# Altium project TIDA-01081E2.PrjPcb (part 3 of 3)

## Sheet TIDA-01081E2_Pre-Boost.SchDoc: Pre-Boost
size 431 x 279 mm; Date: Not shown in title block; ApprovedBy: Not shown in title block; CheckedBy: Not shown in title block; Author: Not shown in title block; CompanyName: Not shown in title block; DrawnBy: SG; Engineer: Not shown in title block; Organization: Not shown in title block; Address1: Not shown in title block; Address2: Not shown in title block; Address3: Not shown in title block; Address4: Not shown in title block; DocumentNumber: 3; Revision: Use project parameter SCH_Rev; SheetNumber: 3; SheetTotal: 8; PageSetup: Record=PageOptions¦CenterHorizontal=True¦CenterVertical=True¦PrintScale=0.94¦XCorrection=1.00¦YCorrection=1.00¦PrintKind=0¦BorderSize=5000000¦LeftOffset=0¦BottomOffset=0¦Orientation=2¦PaperLength=4200¦PaperWidth=2970¦Scale=100¦PaperSource=7¦PrintQuality=600¦MediaType=1¦DitherType=10¦PrintScaleMode=1¦PaperKind=A3¦PaperIndex=8
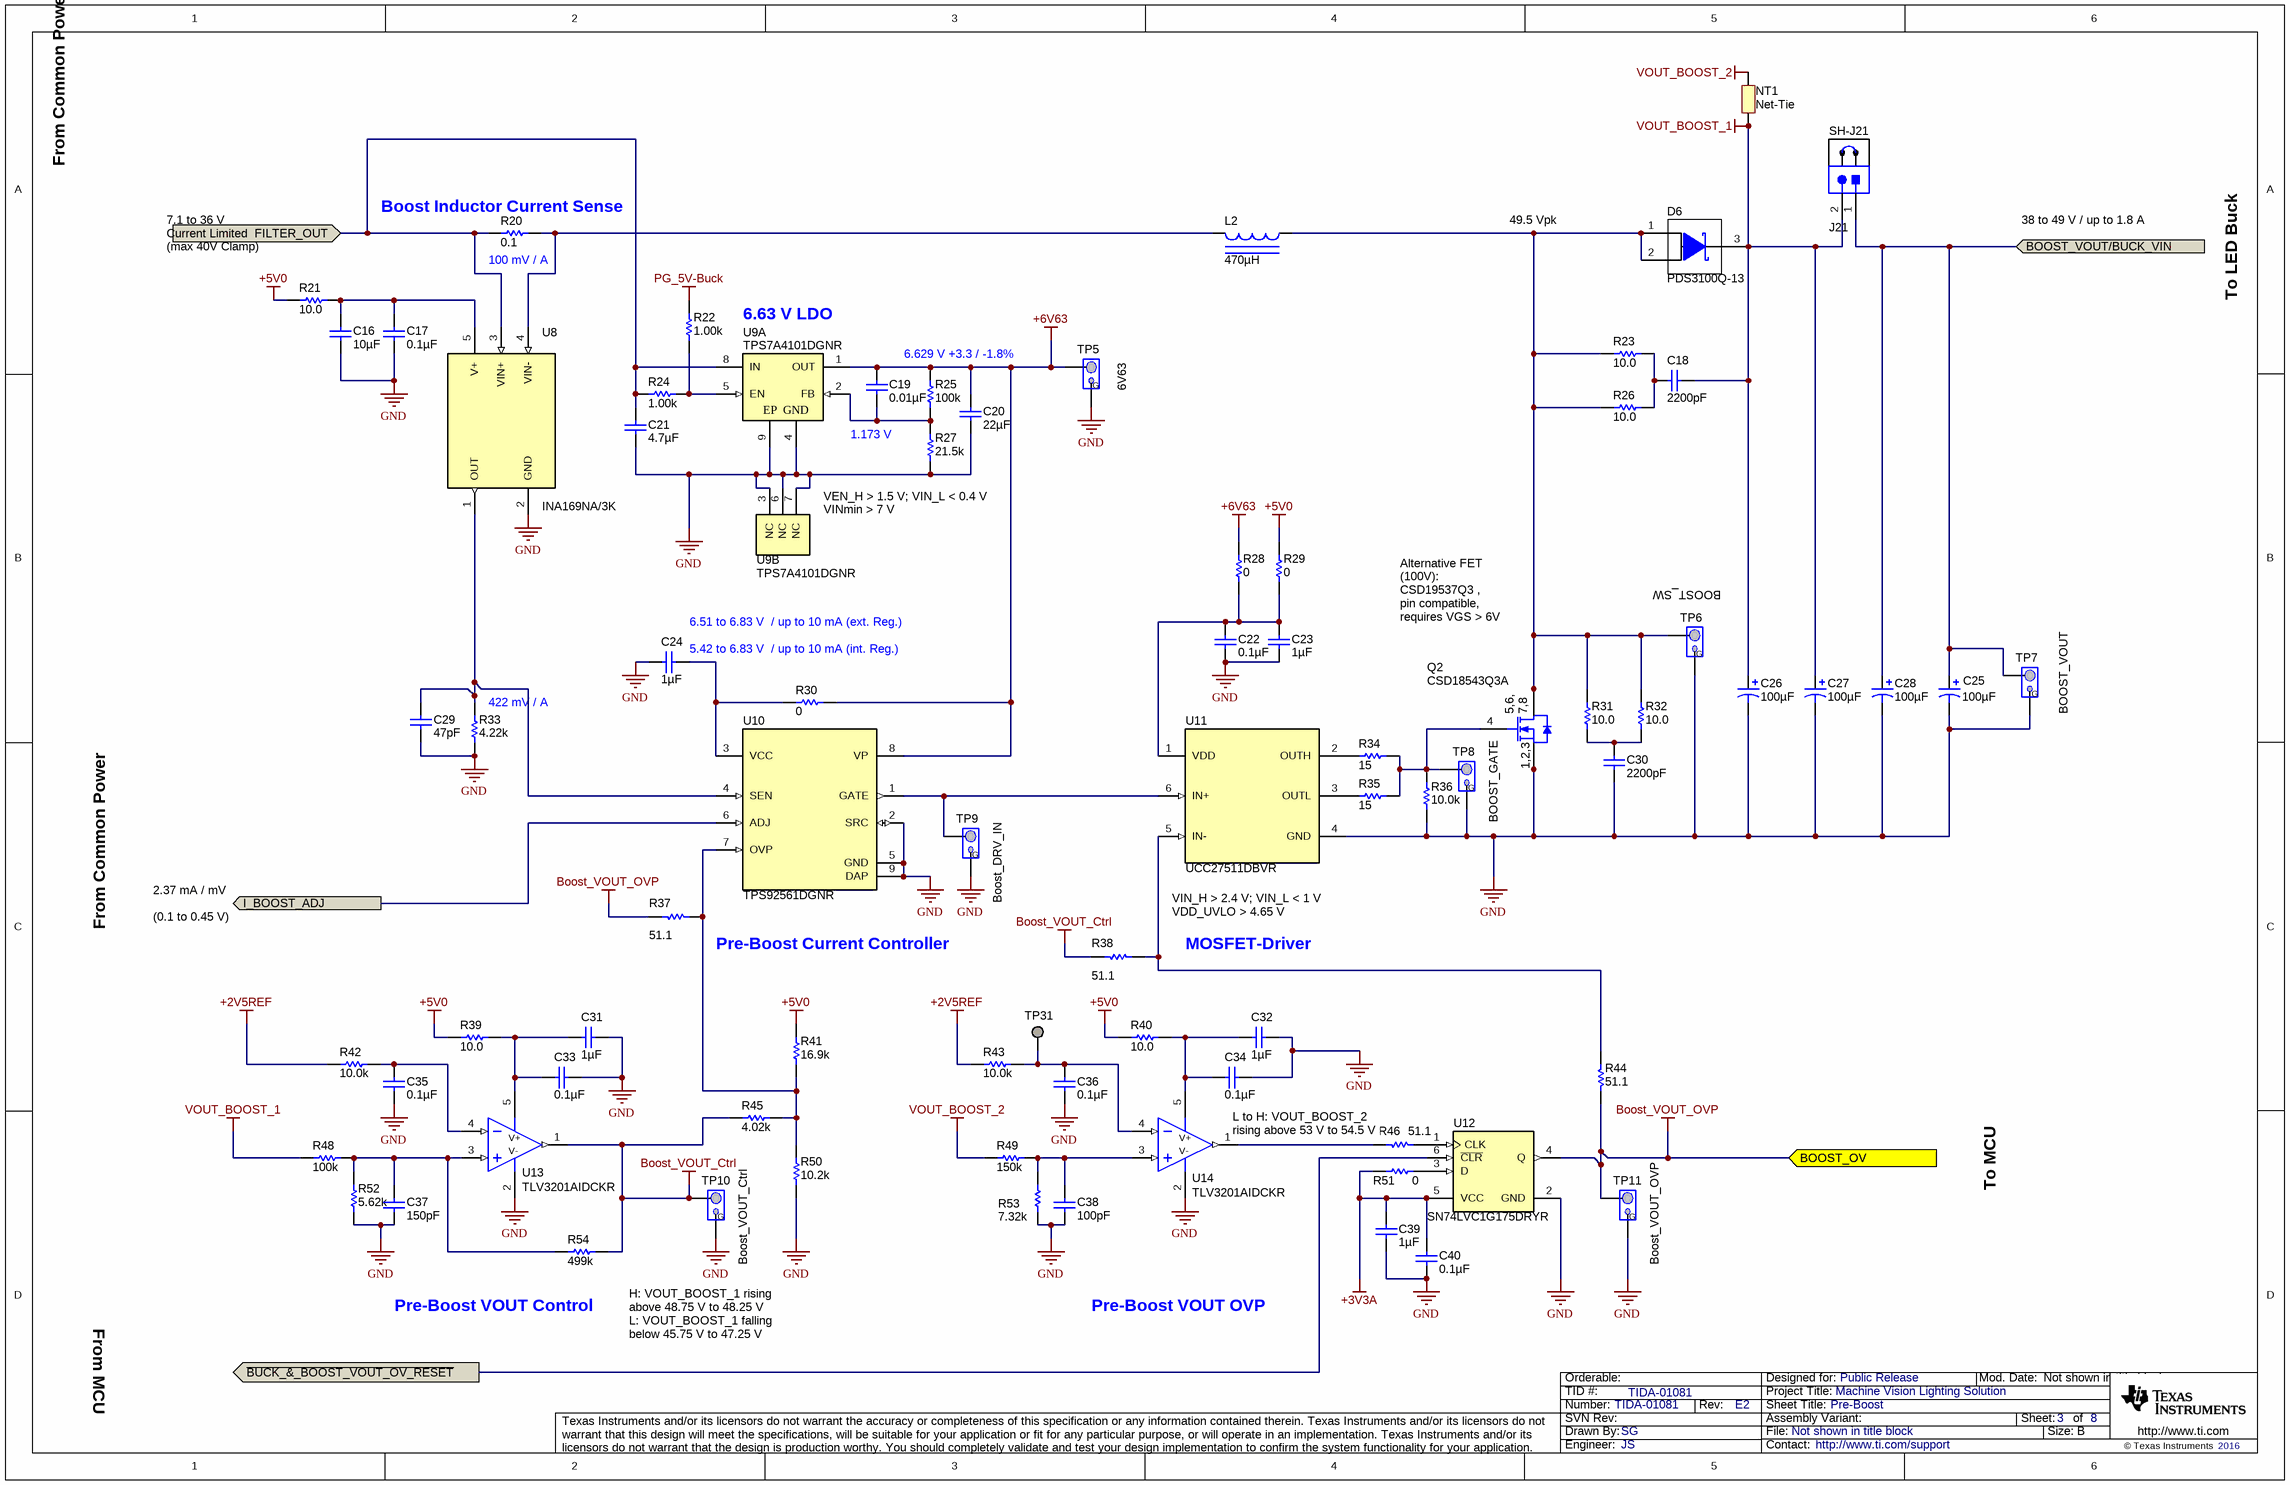
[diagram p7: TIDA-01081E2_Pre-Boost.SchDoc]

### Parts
C16  ValueDisplayed: 10µF  [0603_120]  (hidden comment: ZRB18AD71A106KE01L)
C17  ValueDisplayed: 0.1µF  [0603_HV]  (hidden comment: GCM188R71C104KA37J)
C18  ValueDisplayed: 2200pF  [0603]  (hidden comment: CGA3E2X7R2A222K080AA)
C19  ValueDisplayed: 0.01µF  [0603]  (hidden comment: CL10B103KB8NCNC)
C20  ValueDisplayed: 22µF  [1206_180]  (hidden comment: GRM31CR61E226KE15L)
C21  ValueDisplayed: 4.7µF  [1210_270]  (hidden comment: GRM32ER71K475KE14L)
C22  ValueDisplayed: 0.1µF  [0603_HV]  (hidden comment: GCM188R71C104KA37J)
C23  ValueDisplayed: 1µF  [0603]  (hidden comment: GRM188R71C105KE15D)
C24  ValueDisplayed: 1µF  [0603]  (hidden comment: GRM188R71C105KE15D)
C25  ValueDisplayed: 100µF  [SM_RADIAL_G]  (hidden comment: EEE-FK1J101P)
C26  ValueDisplayed: 100µF  [SM_RADIAL_G]  (hidden comment: EEE-FK1J101P)
C27  ValueDisplayed: 100µF  [SM_RADIAL_G]  (hidden comment: EEE-FK1J101P)
C28  ValueDisplayed: 100µF  [SM_RADIAL_G]  (hidden comment: EEE-FK1J101P)
C29  ValueDisplayed: 47pF  [0603]  (hidden comment: CGA3E2C0G1H470J080AA)
C30  ValueDisplayed: 2200pF  [0603]  (hidden comment: CGA3E2X7R2A222K080AA)
C31  ValueDisplayed: 1µF  [0603S]  (hidden comment: GRM188R71C105KE15D)
C32  ValueDisplayed: 1µF  [0603]  (hidden comment: GRM188R71C105KE15D)
C33  ValueDisplayed: 0.1µF  [0603_HV]  (hidden comment: GCM188R71C104KA37J)
C34  ValueDisplayed: 0.1µF  [0603_HV]  (hidden comment: GCM188R71C104KA37J)
C35  ValueDisplayed: 0.1µF  [0603_HV]  (hidden comment: GCM188R71C104KA37J)
C36  ValueDisplayed: 0.1µF  [0603_HV]  (hidden comment: GCM188R71C104KA37J)
C37  ValueDisplayed: 150pF  [0603]  (hidden comment: C0603C151J5GACTU)
C38  ValueDisplayed: 100pF  [0603]  (hidden comment: 06035A101JAT2A)
C39  ValueDisplayed: 1µF  [0603]  (hidden comment: GRM188R71C105KE15D)
C40  ValueDisplayed: 0.1µF  [0603_HV]  (hidden comment: GCM188R71C104KA37J)
D6  PDS3100Q-13  [PowerDI5]
J21  61300211121  [WURTH_61300211121]  (value not drawn)
L2  ValueDisplayed: 470µH  [WE-PD_1210]  (hidden comment: 7447709471)
NT1  Net-Tie  [Net-Tie_10mil]  (net tie, no BOM)
Q2  CSD18543Q3A  [DNH0008A]
R20  ValueDisplayed: 0.1  [KRL1220]  (hidden comment: KRL1220E-M-R100-F-T5)
R21  ValueDisplayed: 10.0  [0603]  (hidden comment: RC0603FR-0710RL)
R22  ValueDisplayed: 1.00k  [0603]  (hidden comment: RC0603FR-071KL)
R23  ValueDisplayed: 10.0  [0805_HV]  (hidden comment: ERJ-P06F10R0V)
R24  ValueDisplayed: 1.00k  [0603]  (hidden comment: RC0603FR-071KL)
R25  ValueDisplayed: 100k  [0603_HR]  (hidden comment: RR0816P-104-D)
R26  ValueDisplayed: 10.0  [0805_HV]  (hidden comment: ERJ-P06F10R0V)
R27  ValueDisplayed: 21.5k  [0603_HR]  (hidden comment: RR0816P-2152-D-33C)
R28  ValueDisplayed: 0  [0603]  (hidden comment: RC0603JR-070RL)
R29  ValueDisplayed: 0  [0603]  (hidden comment: RC0603JR-070RL)
R30  ValueDisplayed: 0  [0603]  (hidden comment: RC0603JR-070RL)
R31  ValueDisplayed: 10.0  [0805_HV]  (hidden comment: ERJ-P06F10R0V)
R32  ValueDisplayed: 10.0  [0805_HV]  (hidden comment: ERJ-P06F10R0V)
R33  ValueDisplayed: 4.22k  [0603]  (hidden comment: CRCW06034K22FKEA)
R34  ValueDisplayed: 15  [0603]  (hidden comment: CRCW060315R0JNEA)
R35  ValueDisplayed: 15  [0603]  (hidden comment: CRCW060315R0JNEA)
R36  ValueDisplayed: 10.0k  [0603]  (hidden comment: RC0603FR-0710KL)
R37  ValueDisplayed: 51.1  [0603]  (hidden comment: RC0603FR-0751R1L)
R38  ValueDisplayed: 51.1  [0603]  (hidden comment: RC0603FR-0751R1L)
R39  ValueDisplayed: 10.0  [0603]  (hidden comment: RC0603FR-0710RL)
R40  ValueDisplayed: 10.0  [0603]  (hidden comment: RC0603FR-0710RL)
R41  ValueDisplayed: 16.9k  [0603]  (hidden comment: CRCW060316K9FKEA)
R42  ValueDisplayed: 10.0k  [0603]  (hidden comment: RC0603FR-0710KL)
R43  ValueDisplayed: 10.0k  [0603]  (hidden comment: RC0603FR-0710KL)
R44  ValueDisplayed: 51.1  [0603]  (hidden comment: RC0603FR-0751R1L)
R45  ValueDisplayed: 4.02k  [0603]  (hidden comment: CRCW06034K02FKEA)
R46  ValueDisplayed: 51.1  [0603]  (hidden comment: RC0603FR-0751R1L)
R48  ValueDisplayed: 100k  [0603]  (hidden comment: RT0603BRD07100KL)
R49  ValueDisplayed: 150k  [0603]  (hidden comment: RG1608P-154-B-T5)
R50  ValueDisplayed: 10.2k  [0603]  (hidden comment: CRCW060310K2FKEA)
R51  ValueDisplayed: 0  [0603]  (hidden comment: RC0603JR-070RL)
R52  ValueDisplayed: 5.62k  [0603]  (hidden comment: RG1608P-5621-B-T5)
R53  ValueDisplayed: 7.32k  [0603]  (hidden comment: RT0603BRD077K32L)
R54  ValueDisplayed: 499k  [0603]  (hidden comment: RT0603DRE07499KL)
SH-J21  969102-0000-DA  [SNT-100-BK-G]  (value not drawn)
TP5  TESTPOINT_PIGTAIL  [TESTPOINT_PIGTAIL]  (value not drawn)  (no BOM)
TP6  TESTPOINT_PIGTAIL  [TESTPOINT_PIGTAIL]  (value not drawn)  (no BOM)
TP7  TESTPOINT_PIGTAIL  [TESTPOINT_PIGTAIL]  (value not drawn)  (no BOM)
TP8  TESTPOINT_PIGTAIL  [TESTPOINT_PIGTAIL]  (value not drawn)  (no BOM)
TP9  TESTPOINT_PIGTAIL  [TESTPOINT_PIGTAIL]  (value not drawn)  (no BOM)
TP10  TESTPOINT_PIGTAIL  [TESTPOINT_PIGTAIL]  (value not drawn)  (no BOM)
TP11  TESTPOINT_PIGTAIL  [TESTPOINT_PIGTAIL]  (value not drawn)  (no BOM)
TP31  TESTPOINT  [TP_SM_1MM]  (value not drawn)  (no BOM)
U8  INA169NA/3K  [DBV0005A_N]
U9  TPS7A4101DGNR  [DGN0008B_N]  (parts A,B of 2)
U10  TPS92561DGNR  [DGN0008D_N]
U11  UCC27511DBVR  [DBV0006A_N]
U12  SN74LVC1G175DRYR  [DRY0006A]
U13  TLV3201AIDCKR  [DCK0005A_N]
U14  TLV3201AIDCKR  [DCK0005A_N]

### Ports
BOOST_OV, BOOST_VOUT/BUCK_VIN, FILTER_OUT, I_BOOST_ADJ, ~{BUCK_&_BOOST_VOUT_OV_RESET}

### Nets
+2V5REF: R42.2 R43.2
+3V3A: C39.2 C40.1 R51.1 U12.5(VCC)
+5V0: R21.1 R29.2 R39.2 R40.2 R41.2
+6V63: C19.1 C20.1 R25.2 R28.2 R30.2 TP5.1 U9.1(OUT) U10.8(VP)
Boost_VOUT_Ctrl: R38.2 R45.1 R54.2 TP10.1 U13.1(OUT)
Boost_VOUT_OVP: R37.2 R44.2 TP11.1 U12.4(Q) ; port BOOST_OV
FILTER_OUT: C21.1 R20.1 R24.1 U8.3(VIN+) U9.8(IN) ; port FILTER_OUT
GND: C16.2 C17.1 C20.2 C21.2 C22.1 C23.1 C24.2 C25.2(-) C26.2(-) C27.2(-) C28.2(-) C29.2 C30.2 C31.1 C32.1 C33.1 C34.1 C35.2 C36.2 C37.1 C38.1 C39.1 C40.2 Q2.1(S) Q2.2(S) Q2.3(S) R27.1 R33.1 R36.1 R50.1 R52.1 R53.1 TP5.2 TP6.2 TP7.2 TP8.2 TP9.2 TP10.2 TP11.2 U8.2(GND) U9.3(NC) U9.4(GND) U9.6(NC) U9.7(NC) U9.9(EP) U10.2(SRC) U10.5(GND) U10.9(DAP) U11.4(GND) U12.2(GND) U13.2(V-) U14.2(V-)
PG_5V-Buck: R22.1
VOUT_BOOST_1: C18.2 C26.1(+) C27.1(+) D6.3(K) J21.2 NT1.1 R48.1
VOUT_BOOST_2: NT1.2 R49.1
~{BUCK_&_BOOST_VOUT_OV_RESET}: U12.6(~{CLR}) ; port ~{BUCK_&_BOOST_VOUT_OV_RESET}
BOOST_VOUT/BUCK_VIN: C25.1(+) C28.1(+) J21.1 TP7.1 ; port BOOST_VOUT/BUCK_VIN
I_BOOST_ADJ: U10.6(ADJ) ; port I_BOOST_ADJ
NetC16_1: C16.1 C17.2 R21.2 U8.5(V+)
NetC18_1: C18.1 R23.1 R26.1
NetC19_2: C19.2 R25.1 R27.2 U9.2(FB)
NetC22_2: C22.2 C23.2 R28.1 R29.1 U11.1(VDD)
NetC24_1: C24.1 R30.1 U10.3(VCC)
NetC29_1: C29.1 R33.2 U8.1(OUT) U10.4(SEN)
NetC30_1: C30.1 R31.1 R32.1
NetC31_2: C31.2 C33.2 R39.1 U13.5(V+)
NetC32_2: C32.2 C34.2 R40.1 U14.5(V+)
NetC35_1: C35.1 R42.1 U13.4(IN-)
NetC36_1: C36.1 R43.1 TP31.1 U14.4(IN-)
NetC37_2: C37.2 R48.2 R52.2 R54.1 U13.3(IN+)
NetC38_2: C38.2 R49.2 R53.2 U14.3(IN+)
NetD6_1: D6.1(A) D6.2(A) L2.1 Q2.5(D) Q2.6(D) Q2.7(D) Q2.8(D) Q2.9(D) R23.2 R26.2 R31.2 R32.2 TP6.1
NetL2_2: L2.2 R20.2 U8.4(VIN-)
NetQ2_4: Q2.4(G) R34.2 R35.2 R36.2 TP8.1
NetR22_2: R22.2 R24.2 U9.5(EN)
NetR34_1: R34.1 U11.2(OUTH)
NetR35_1: R35.1 U11.3(OUTL)
NetR37_1: R37.1 R41.1 R45.2 R50.2 U10.7(OVP)
NetR38_1: R38.1 R44.1 U11.5(IN-)
NetR46_1: R46.1 U12.1(CLK)
NetR46_2: R46.2 U14.1(OUT)
NetR51_2: R51.2 U12.3(D)
NetTP9_1: TP9.1 U10.1(GATE) U11.6(IN+)

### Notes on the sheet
- From Common Power
- 7.1 to 36 V
- Current Limited
- (near R20) Boost Inductor Current Sense
- 49.5 Vpk
- 38 to 49 V / up to 1.8 A
- (max 40V Clamp)
- (near R20) 100 mV / A
- To LED Buck
- 6.63 V LDO
- 6.629 V +3.3 / -1.8%
- 1.173 V
- (near TP5) 6V63
- VEN_H > 1.5 V; VIN_L < 0.4 V
  VINmin > 7 V
- (near C24) 6.51 to 6.83 V  / up to 10 mA (ext. Reg.)
- Alternative FET (100V):
  CSD19537Q3 ,
  pin compatible,
  requires VGS > 6V
- (near TP6) BOOST_SW
- (near R33) 422 mV / A
- (near C24) 5.42 to 6.83 V  / up to 10 mA (int. Reg.)
- (near TP7) BOOST_VOUT
- BOOST_GATE
- 2.37 mA / mV
- (near TP9) Boost_DRV_IN
- (0.1 to 0.45 V)
- (near R37) Pre-Boost Current Controller
- VIN_H > 2.4 V; VIN_L < 1 V
  VDD_UVLO > 4.65 V
- MOSFET-Driver
- L to H: VOUT_BOOST_2 rising above 53 V to 54.5 V
- To MCU
- (near R54) Pre-Boost VOUT Control
- (near TP10) Boost_VOUT_Ctrl
- Pre-Boost VOUT OVP
- (near TP11) Boost_VOUT_OVP
- From MCU
- H: VOUT_BOOST_1 rising above 48.75 V to 48.25 V
  L: VOUT_BOOST_1 falling below 45.75 V to 47.25 V

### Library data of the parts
C16 = ZRB18AD71A106KE01L: CAP, CERM, 10 µF, 10 V, +/- 10%, X7T, 0603; Manufacturer: MuRata; Polarized: N; CompType: Capacitor; Value: 10uF; U/M: EA; Cap_F: 0.00001; Tolerance_%: 10; Value1: Unknown; Value2: 10V; TaMin_C: -55; TaMax_C: 125; Cap_Case: 0603; SizeArea_mm2: 1.28; SizeAreaWB_mm2: 4.68; SizeX_mm: 1.6; SizeY_mm: 0.8; SizeZ_mm: 1.2; AEC Category: Q200
C17 C22 C33-C36 C40 = GCM188R71C104KA37J: CAP, CERM, 0.1 µF, 16 V, +/- 10%, X7R, 0603_095; Manufacturer: MuRata; Polarized: N; CompType: Capacitor; Value: 0.1uF; U/M: EA; Cap_F: 0.0000001; Tolerance_%: 10; Value1: Unknown; VDC_V: 16; Value2: 16V; TaMin_C: -55; TaMax_C: 125; Cap_Case: 0603
C18 C30 = CGA3E2X7R2A222K080AA: CAP, CERM, 2200 pF, 100 V, +/- 10%, X7R, AEC-Q200 Grade 1, 0603; Manufacturer: TDK; Polarized: N; CompType: Capacitor; Value: 2200pF; U/M: EA; Cap_F: 0.0000000022; Tolerance_%: 10; ESR_ohm: 0.923948; Value1: 0.923948 ohm; VDC_V: 100; Value2: 100V; IRMS_A: 0.295638; TaMin_C: -55; TaMax_C: 125; SizeArea_mm2: 1.28; SizeAreaWB_mm2: 4.68; SizeX_mm: 1.6; SizeY_mm: 0.8; SizeZ_mm: 1; AEC Category: Q200; AEC Qualified: Y
C19 = CL10B103KB8NCNC: CAP, CERM, 0.01 µF, 50 V, +/- 10%, X7R, 0603; Manufacturer: Samsung Electro-Mechanics; Polarized: N; CompType: Capacitor; Value: 0.01uF; U/M: EA; Cap_F: 0.00000001; Tolerance_%: 10; Value1: Unknown; VDC_V: 50; Value2: 50V; TaMin_C: -55; TaMax_C: 125; SizeArea_mm2: 1.28; SizeAreaWB_mm2: 4.68; SizeX_mm: 1.6; SizeY_mm: 0.8; SizeZ_mm: 1; AEC Category: Q200; Green_Lifecycle: Active; Green_REACh: Passed
C20 = GRM31CR61E226KE15L: CAP, CERM, 22 µF, 25 V, +/- 10%, X5R, 1206; Manufacturer: MuRata; Polarized: N; CompType: Capacitor; Value: 22uF; U/M: EA; Cap_F: 0.000022; Tolerance_%: 10; Value1: Unknown; VDC_V: 25; Value2: 25V; TaMin_C: -55; TaMax_C: 85; Cap_Case: 1206; SizeArea_mm2: 5.12; SizeAreaWB_mm2: 10.92; SizeX_mm: 3.2; SizeY_mm: 1.6; SizeZ_mm: 1.8; AEC Category: Q200; Green_Lifecycle: Active; Green_REACh: Passed
C21 = GRM32ER71K475KE14L: CAP, CERM, 4.7 µF, 80 V, +/- 10%, X7R, 1210; Manufacturer: MuRata; Polarized: N; CompType: Capacitor; Value: 4.7uF; U/M: EA; Cap_F: 0.0000047; Tolerance_%: 10; Value1: Unknown; VDC_V: 80; Value2: 80V; TaMin_C: -55; TaMax_C: 125; Cap_Case: 1210; SizeArea_mm2: 8; SizeAreaWB_mm2: 14.7; SizeX_mm: 3.2; SizeY_mm: 2.5; SizeZ_mm: 2.7; AEC Category: Q200
C23 C24 C32 C39 = GRM188R71C105KE15D: CAP, CERM, 1 µF, 16 V, +/- 10%, X7R, 0603; Manufacturer: MuRata; Polarized: N; CompType: Capacitor; Value: 1uF; U/M: EA; Cap_F: 0.000001; Tolerance_%: 10; Value1: Unknown; VDC_V: 16; Value2: 16V; TaMin_C: -55; TaMax_C: 125; SizeArea_mm2: 1.28; SizeAreaWB_mm2: 4.68; SizeX_mm: 1.6; SizeY_mm: 0.8; SizeZ_mm: 1; AEC Category: Q200
C25-C28 = EEE-FK1J101P: CAP, AL, 100 µF, 63 V, +/- 20%, 0.35 ohm, AEC-Q200 Grade 2, SMD; Manufacturer: Panasonic; Polarized: Y; CompType: Capacitor; Value: 100uF; U/M: EA; Cap_F: 0.0001; Tolerance_%: 20; VDC_V: 63; Value2: 63V; ESR_ohm: 0.35; IRMS_A: 0.4; TaMin_C: -55; TaMax_C: 105; Cap_Case: G; SizeAreaWB_mm2: 172.2; SizeArea_mm2: 123.6; SizeX_mm: 12; SizeY_mm: 10.3; SizeZ_mm: 10.2; AEC Category: Q200; AEC Grade: 2
C29 = CGA3E2C0G1H470J080AA: CAP, CERM, 47 pF, 50 V, +/- 5%, C0G/NP0, AEC-Q200 Grade 1, 0603; Manufacturer: TDK; Polarized: N; CompType: Capacitor; Value: 47pF; U/M: EA; Cap_F: 0.000000000047; Tolerance_%: 5; Value1: Unknown; VDC_V: 50; Value2: 50V; TaMin_C: -55; TaMax_C: 125; SizeArea_mm2: 1.28; SizeAreaWB_mm2: 4.68; SizeX_mm: 1.6; SizeY_mm: 0.8; SizeZ_mm: 1; AEC Category: Q200; AEC Qualified: Y
C31 = GRM188R71C105KE15D: CAP, CERM, 1 µF, 16 V, +/- 10%, X7R, 0603; Manufacturer: MuRata; Polarized: N; CompType: Capacitor; Value: 1uF; U/M: EA; Cap_F: 0.000001; Tolerance_%: 10; Value1: Unknown; VDC_V: 16; Value2: 16V; TaMin_C: -55; TaMax_C: 125; Cap_Case: 0603; SizeArea_mm2: 1.28; SizeAreaWB_mm2: 4.68; SizeX_mm: 1.6; SizeY_mm: 0.8; SizeZ_mm: 1; AEC Category: Q200
C37 = C0603C151J5GACTU: CAP, CERM, 150 pF, 50 V,+/- 5%, C0G/NP0, 0603; Manufacturer: Kemet; Polarized: N; CompType: Capacitor; Value: 150pF; U/M: EA; Cap_F: 0.00000000015; Tolerance_%: 5; Value1: Unknown; VDC_V: 50; Value2: 50V; TaMin_C: -55; TaMax_C: 125; SizeArea_mm2: 1.28; SizeAreaWB_mm2: 4.68; SizeX_mm: 1.6; SizeY_mm: 0.8; SizeZ_mm: 1; AEC Category: Q200; Green_Lifecycle: Active; Green_REACh: Passed
C38 = 06035A101JAT2A: CAP, CERM, 100 pF, 50 V,+/- 5%, C0G/NP0, 0603; Manufacturer: AVX; Polarized: N; CompType: Capacitor; Value: 100pF; U/M: EA; Cap_F: 0.0000000001; Tolerance_%: 5; ESR_ohm: 0.119; Value1: 0.119 ohm; VDC_V: 50; Value2: 50V; TaMin_C: -55; TaMax_C: 125; SizeArea_mm2: 1.28; SizeAreaWB_mm2: 4.68; SizeX_mm: 1.6; SizeY_mm: 0.8; SizeZ_mm: 1; AEC Category: Q200; Green_Lifecycle: Active; Green_REACh: Passed
D6 = PDS3100Q-13: Diode, Schottky, 100 V, 3 A, AEC-Q101, PowerDI5; Manufacturer: Diodes Inc.; U/M: EA; Vf_V: 0.76; Value: 100V; Value1: 3A; Value2: 0.76V; Io_A: 3; Vr_V: 100; TJmax_C: 150; SizeAreaWB_mm2: 49.56; SizeArea_mm2: 24.96; SizeX_mm: 6.4; SizeY_mm: 3.9; SizeZ_mm: 1.05; AEC Category: Q101; AEC Qualified: Y
J21 = 61300211121: Header, 2.54 mm, 2x1, Gold, TH; Manufacturer: Wurth Elektronik; SymbolCreator: a0412235
L2 = 7447709471: Inductor, Shielded Drum Core, Ferrite, 470 µH, 1.4 A, 0.56 ohm, SMD; Manufacturer: Wurth Elektronik; Value: 470uH; Ind_H: 470.0E-6; Imax_A: 1.4; Irms: 1.4A @ 40C rise; Isat: 1.5A @ 10% inductance drop; DCR_ohm: 0.56; Value2: 1.4A; SizeAreaWB_mm2: 196; SizeArea_mm2: 144; SizeX_mm: 12; SizeZ_mm: 10; AEC Category: Q200; Green_Lifecycle: Active; Green_REACh: Passed
NT1 = Net-Tie: Single point connection between nets.; SymbolCreator: codlsc
Q2 = CSD18543Q3A: MOSFET, N-CH, 60 V, 35 A, DNH0008A (VSONP-8); Manufacturer: Texas Instruments; Alternate Manufacturer: None; U/M: EA; ChType: N; Value: 60V; VdsMax_V: 60; Value1: 0.012 ohm; Rdson45_ohm: 0.012; Value2: 11.1 nC; QgTyp_nC: 11.1; Vgs_V: 20; IdsMax_A: 35; SizeAreaWB_mm2: 18.49; SizeArea_mm2: 10.89; SizeX_mm: 3.3; SizeZ_mm: 0.9; AEC Category: Q101
R20 = KRL1220E-M-R100-F-T5: RES, 0.1, 1%, 0.5 W, AEC-Q200 Grade 0, 0805; Manufacturer: Susumu Co Ltd; CompType: Resistor; Value: 0.1; Value_Code: R100; Tolerance_%: 1; Power_W: 0.5; Value2: 0.5W; TempCo: 50 ppm/C; SizeArea_mm2: 2.5; SizeX_mm: 2; SizeY_mm: 1.25; SizeZ_mm: 0.7; EIA_Code: E96; U/M: EA; AEC Category: Q200; AEC Qualified: Y; AEC Grade: 0
R21 R39 R40 = RC0603FR-0710RL: RES, 10.0, 1%, 0.1 W, 0603; Manufacturer: Yageo America; CompType: Resistor; Value: 10.0; Res_ohm: 10; Value_Code: 10R0; Tolerance_%: 1; Power_W: 0.1; Value2: 0.1W; VDC_V: 150; TempCo: 200 ppm/C; SizeArea_mm2: 1.28; SizeX_mm: 1.6; SizeY_mm: 0.8; EIA_Code: E96; U/M: EA; AEC Category: Q200; Green_Lifecycle: Active; Green_REACh: Passed
R22 R24 = RC0603FR-071KL: RES, 1.00 k, 1%, 0.1 W, 0603; Manufacturer: Yageo America; CompType: Resistor; Value: 1.00k; Res_ohm: 1000; Value_Code: 1k00; Tolerance_%: 1; Power_W: 0.1; Value2: 0.1W; VDC_V: 150; TempCo: 200 ppm/C; SizeArea_mm2: 1.28; SizeX_mm: 1.6; SizeY_mm: 0.8; EIA_Code: E96; U/M: EA; AEC Category: Q200; Green_Lifecycle: Active; Green_REACh: Passed
R23 R26 R31 R32 = ERJ-P06F10R0V: RES, 10.0, 1%, 0.5 W, AEC-Q200 Grade 0, 0805; Manufacturer: Panasonic; CompType: Resistor; Value: 10.0; Res_ohm: 10; Value_Code: 10R0; Tolerance_%: 1; Power_W: 0.5; Value2: 0.5W; TempCo: 300 ppm/C; SizeArea_mm2: 2.5; SizeX_mm: 2; SizeY_mm: 1.25; SizeZ_mm: 1.45; EIA_Code: E96; U/M: EA; AEC Category: Q200; AEC Qualified: Y; AEC Grade: 0
R25 = RR0816P-104-D: RES, 100 k, 0.5%, 0.0625 W, 0603; Manufacturer: Susumu Co Ltd; CompType: Resistor; Value: 100k; Res_ohm: 100000; Tolerance_%: 0.5; Power_W: 0.0625; VDC_V: 75; TempCo: 25 ppm/C; SizeArea_mm2: 1.3175; SizeX_mm: 1.55; SizeY_mm: 0.85; EIA_Code: E192; U/M: EA; AEC Category: Q200; AEC Qualified: N; Green_Lifecycle: Active; Green_REACh: Passed
R27 = RR0816P-2152-D-33C: RES, 21.5 k, 0.5%, 0.0625 W, 0603; Manufacturer: Susumu Co Ltd; CompType: Resistor; Value: 21.5k; Res_ohm: 21500; Value_Code: 21k5; Tolerance_%: 0.5; Power_W: 0.0625; VDC_V: 75; TempCo: 25 ppm/C; SizeArea_mm2: 1.3175; SizeX_mm: 1.55; SizeY_mm: 0.85; EIA_Code: E192; U/M: EA; AEC Category: Q200; AEC Qualified: N; Green_Lifecycle: Active; Green_REACh: Passed
R28-R30 R51 = RC0603JR-070RL: RES, 0, 5%, 0.1 W, 0603; Manufacturer: Yageo America; CompType: Resistor; Value: 0; Value_Code: 0000; Tolerance_%: 5; Power_W: 0.1; Value2: 0.1W; VDC_V: 50; TempCo: 200 ppm/C; SizeArea_mm2: 1.28; SizeX_mm: 1.6; SizeY_mm: 0.8; SizeZ_mm: 1; EIA_Code: E24; U/M: EA; AEC Category: Q200; Green_Lifecycle: Active; Green_REACh: Passed
R33 = CRCW06034K22FKEA: RES, 4.22 k, 1%, 0.1 W, 0603; Manufacturer: Vishay-Dale; CompType: Resistor; Value: 4.22k; Res_ohm: 4220; Value_Code: 4k22; Tolerance_%: 1; Power_W: 0.1; Value2: 0.1W; VDC_V: 75; TempCo: 100 ppm/C; SizeArea_mm2: 1.28; SizeX_mm: 1.6; SizeY_mm: 0.8; EIA_Code: E96; U/M: EA; AEC Category: Q200; Green_Lifecycle: Active; Green_REACh: Passed
R34 R35 = CRCW060315R0JNEA: RES, 15, 5%, 0.1 W, 0603; Manufacturer: Vishay-Dale; CompType: Resistor; Value: 15; Value_Code: 15R0; Tolerance_%: 5; Power_W: 0.1; Value2: 0.1W; VDC_V: 75; TempCo: 200 ppm/C; SizeArea_mm2: 1.28; SizeX_mm: 1.6; SizeY_mm: 0.8; SizeZ_mm: 1; EIA_Code: E24; U/M: EA; AEC Category: Q200; Green_Lifecycle: Active; Green_REACh: Passed
R36 R42 R43 = RC0603FR-0710KL: RES, 10.0 k, 1%, 0.1 W, 0603; Manufacturer: Yageo America; CompType: Resistor; Value: 10.0k; Res_ohm: 10000; Value_Code: 10k0; Tolerance_%: 1; Power_W: 0.1; Value2: 0.1W; VDC_V: 150; TempCo: 200 ppm/C; SizeArea_mm2: 1.28; SizeX_mm: 1.6; SizeY_mm: 0.8; EIA_Code: E96; U/M: EA; AEC Category: Q200; Green_Lifecycle: Active; Green_REACh: Passed
R37 R38 R44 R46 = RC0603FR-0751R1L: RES, 51.1, 1%, 0.1 W, 0603; Manufacturer: Yageo America; CompType: Resistor; Value: 51.1; Value_Code: 51R1; Tolerance_%: 1; Power_W: 0.1; Value2: 0.1W; VDC_V: 150; TempCo: 200 ppm/C; SizeArea_mm2: 1.28; SizeX_mm: 1.6; SizeY_mm: 0.8; EIA_Code: E96; U/M: EA; AEC Category: Q200; Green_Lifecycle: Active; Green_REACh: Passed
R41 = CRCW060316K9FKEA: RES, 16.9 k, 1%, 0.1 W, 0603; Manufacturer: Vishay-Dale; CompType: Resistor; Value: 16.9k; Res_ohm: 16900; Value_Code: 16k9; Tolerance_%: 1; Power_W: 0.1; Value2: 0.1W; VDC_V: 75; TempCo: 100 ppm/C; SizeArea_mm2: 1.28; SizeX_mm: 1.6; SizeY_mm: 0.8; EIA_Code: E96; U/M: EA; AEC Category: Q200; Green_Lifecycle: Active; Green_REACh: Passed
R45 = CRCW06034K02FKEA: RES, 4.02 k, 1%, 0.1 W, 0603; Manufacturer: Vishay-Dale; CompType: Resistor; Value: 4.02k; Res_ohm: 4020; Value_Code: 4k02; Tolerance_%: 1; Power_W: 0.1; Value2: 0.1W; VDC_V: 75; TempCo: 100 ppm/C; SizeArea_mm2: 1.28; SizeX_mm: 1.6; SizeY_mm: 0.8; EIA_Code: E96; U/M: EA; AEC Category: Q200; Green_Lifecycle: Active; Green_REACh: Passed
R48 = RT0603BRD07100KL: RES, 100 k, 0.1%, 0.1 W, 0603; Manufacturer: Yageo America; CompType: Resistor; Value: 100k; Res_ohm: 100000; Tolerance_%: 0.1; Value2: 0.1W; VDC_V: 75; TempCo: 25 ppm/C; SizeArea_mm2: 1.28; SizeX_mm: 1.6; SizeY_mm: 0.8; SizeZ_mm: 1; EIA_Code: E192; U/M: EA; AEC Category: Q200; Green_Lifecycle: Active; Green_REACh: Passed
R49 = RG1608P-154-B-T5: RES, 150 k, 0.1%, 0.1 W, 0603; Manufacturer: Susumu Co Ltd; CompType: Resistor; Value: 150k; Res_ohm: 150000; Tolerance_%: 0.1; Value2: 0.1W; VDC_V: 75; TempCo: 25 ppm/C; SizeArea_mm2: 1.28; SizeX_mm: 1.6; SizeY_mm: 0.8; SizeZ_mm: 1; EIA_Code: E192; U/M: EA; AEC Category: Q200; Green_Lifecycle: Active; Green_REACh: Passed
R50 = CRCW060310K2FKEA: RES, 10.2 k, 1%, 0.1 W, 0603; Manufacturer: Vishay-Dale; CompType: Resistor; Value: 10.2k; Res_ohm: 10200; Value_Code: 10k2; Tolerance_%: 1; Power_W: 0.1; Value2: 0.1W; VDC_V: 75; TempCo: 100 ppm/C; SizeArea_mm2: 1.28; SizeX_mm: 1.6; SizeY_mm: 0.8; EIA_Code: E96; U/M: EA; AEC Category: Q200; Green_Lifecycle: Active; Green_REACh: Passed
R52 = RG1608P-5621-B-T5: RES, 5.62 k, 0.1%, 0.1 W, 0603; Manufacturer: Susumu Co Ltd; CompType: Resistor; Value: 5.62k; Res_ohm: 5620; Value_Code: 5k62; Tolerance_%: 0.1; Value2: 0.1W; VDC_V: 75; TempCo: 25 ppm/C; SizeArea_mm2: 1.28; SizeX_mm: 1.6; SizeY_mm: 0.8; SizeZ_mm: 1; EIA_Code: E192; U/M: EA; AEC Category: Q200
R53 = RT0603BRD077K32L: RES, 7.32 k, 0.1%, 0.1 W, 0603; Manufacturer: Yageo America; CompType: Resistor; Value: 7.32k; Res_ohm: 7320; Value_Code: 7k32; Tolerance_%: 0.1; Value2: 0.1W; VDC_V: 75; TempCo: 25 ppm/C; SizeArea_mm2: 1.28; SizeX_mm: 1.6; SizeY_mm: 0.8; SizeZ_mm: 1; EIA_Code: E192; U/M: EA; AEC Category: Q200
R54 = RT0603DRE07499KL: RES, 499 k, 0.5%, 0.1 W, 0603; Manufacturer: Yageo America; CompType: Resistor; Value: 499k; Res_ohm: 499000; Tolerance_%: 0.5; Power_W: 0.1; Value2: 0.1W; VDC_V: 75; TempCo: 50 ppm/C; SizeArea_mm2: 1.28; SizeX_mm: 1.6; SizeY_mm: 0.8; SizeZ_mm: 1; EIA_Code: E192; U/M: EA; AEC Category: Q200
SH-J21 = 969102-0000-DA: Shunt, 100mil, Gold plated, Black; Manufacturer: 3M; Alternate Manufacturer: Samtec; Value: 1x2; Note: You can "mate" this to a header by matching the designator.  i.e. use SH-J3 for header J3
TP5-TP11 = TESTPOINT_PIGTAIL: PIGTAIL; Manufacturer: Texas Instruments; SymbolCreator: Altium
TP31 = TP_SM_1MM: 1mm Test Point, SMT; Manufacturer: Any
U8 = INA169NA/3K: 60-V, High-Side, High-Speed, Current Output Current Shunt Monitor, DBV0005A (SOT-23-5); Alternate PartNumber: INA169NA/250; Manufacturer: Texas Instruments; SymbolCreator: a0411947; SizeArea_mm2: 8.12; SizeAreaWB_mm2: 14.82; SizeX_mm: 2.8; SizeY_mm: 2.9; SizeZ_mm: 1.45; CompType: IC; U/M: EA
U9 = TPS7A4101DGNR: Single Output LDO, 50 mA, Adjustable 1.175 to 48 V Output, 7 to 50 V Input, 8-pin MSOP (DGN), -40 to 125 degC, Green (RoHS & no Sb/Br); Manufacturer: Texas Instruments; Alternate PartNumber: Equivalent; Accuracy(%): 1; Iout(Max)(A): 0.05; Iq(Typ)(mA): 0.02; SubFamily: Single Channel LDO; Vdo(Typ)(mV): 290; Vin(Max)(V): 50; Vin(Min)(V): 7; Vout Adj(Max)(V): 48; Vout Adj(Min)(V): 1.161
U10 = TPS92561DGNR: Phase Dimmable, Single Stage Boost Controller for LED Lighting, DGN0008D (VSSOP-8); Manufacturer: Texas Instruments; SymbolCreator: a0799628; SizeArea_mm2: 15.655; SizeAreaWB_mm2: 35.955; SizeX_mm: 5.05; SizeY_mm: 3.1; SizeZ_mm: 1.1; CompType: IC; U/M: EA
U11 = UCC27511DBVR: 4A/8A Single Channel High-speed Low-side Gate Driver, DBV0006A (SOT-23-6); Alternate PartNumber: UCC27511DBVT; Manufacturer: Texas Instruments; SymbolCreator: a0411947; SizeArea_mm2: 8.12; SizeAreaWB_mm2: 14.82; SizeX_mm: 2.8; SizeY_mm: 2.9; SizeZ_mm: 1.45; CompType: IC; U/M: EA
U12 = SN74LVC1G175DRYR: Single D-Type Flip-Flop with Asynchronous Clear, DRY0006A, LARGE T&R; Manufacturer: Texas Instruments; Alternate PartNumber: Equivalent; VCC(Min)(V): 1.65; VCC(Max)(V): 5.5; Output Type: CMOS; ICC @ Nom Voltage(Max)(mA): 0.01; Input Type: CMOS/TTL; Bits(#): 1; F @ Nom Voltage(Max)(Mhz): 150; Rating: Catalog; Technology Family: LVC; Voltage(Nom)(V): 1.8,2.5,3.3,5; Schmitt Trigger: No; Output Drive (IOL/IOH)(Max)(mA): 32/-32; tpd @ Nom Voltage(Max)(ns): 13.4,7.1,5.7,4; Logic: True
U13 U14 = TLV3201AIDCKR: 40ns, micro-Power, Rail-to-Rail Input, Single-Channel Comparator with Push-Pull Outputs, DCK0005A (SOT-SC70-5); Alternate PartNumber: TLV3201AIDCKT; Manufacturer: Texas Instruments; SizeArea_mm2: 4.2; SizeAreaWB_mm2: 9.3; SizeX_mm: 2.1; SizeY_mm: 2; SizeZ_mm: 1.1; CompType: IC; U/M: EA

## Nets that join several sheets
5V-LS_ON: TIDA-01081E2_CommonPower (R124.2 U32.5), TIDA-01081E2_Controller (U21.36)
+2V5REF: TIDA-01081E2_CommonPower (C80.1 R109.1 TP21.1 U30.2), TIDA-01081E2_Controller (R88.2), TIDA-01081E2_LED_Buck (R126.1), TIDA-01081E2_Pre-Boost (R42.2 R43.2)
+3V3A: TIDA-01081E2_CommonPower (6 pins), TIDA-01081E2_Controller (8 pins), TIDA-01081E2_LED_Board (J4.6 R55.1 R56.1), TIDA-01081E2_LED_Buck (5 pins), TIDA-01081E2_Pre-Boost (C39.2 C40.1 R51.1 U12.5)
+5V0: TIDA-01081E2_CommonPower (R96.2 R119.2 TP23.1 U32.1), TIDA-01081E2_Controller (J10.4 R80.2), TIDA-01081E2_DigitalIO (C96.1 R138.2), TIDA-01081E2_LED_Board (12 pins), TIDA-01081E2_LED_Buck (6 pins), TIDA-01081E2_Pre-Boost (5 pins)
ALERT: TIDA-01081E2_Controller (J9.2 R73.1 U21.29), TIDA-01081E2_LED_Board (J4.2 U15.3 U16.3), TIDA-01081E2_LED_Buck (U1.3 U2.3)
Boost_VOUT_OVP: TIDA-01081E2_Controller (U21.38), TIDA-01081E2_Pre-Boost (R37.2 R44.2 TP11.1 U12.4)
BUCK_DISCHG_COFF: TIDA-01081E2_Controller (U21.20), TIDA-01081E2_LED_Buck (R60.2)
BUCK_VOUT: TIDA-01081E2_Controller (R75.2), TIDA-01081E2_LED_Buck (9 pins)
FILTER_OUT: TIDA-01081E2_CommonPower (7 pins), TIDA-01081E2_Pre-Boost (5 pins)
GND: TIDA-01081E2_CommonPower (56 pins), TIDA-01081E2_Controller (26 pins), TIDA-01081E2_DigitalIO (6 pins), TIDA-01081E2_LED_Board (39 pins), TIDA-01081E2_LED_Buck (43 pins), TIDA-01081E2_Pre-Boost (52 pins)
PG_5V-Buck: TIDA-01081E2_CommonPower (R111.1 R112.1 TP19.1 U31.6), TIDA-01081E2_Pre-Boost (R22.1)
SCL: TIDA-01081E2_Controller (J9.3 R72.1 U21.6), TIDA-01081E2_LED_Board (J4.3 U15.1 U16.1 U16.4), TIDA-01081E2_LED_Buck (U1.1 U2.1)
SDA: TIDA-01081E2_Controller (J9.4 R71.1 U21.5), TIDA-01081E2_LED_Board (J4.4 U15.4 U15.6 U16.6), TIDA-01081E2_LED_Buck (U1.6 U2.6)
~{BUCK_&_BOOST_VOUT_OV_RESET}: TIDA-01081E2_Controller (U21.13), TIDA-01081E2_LED_Buck (U7.6), TIDA-01081E2_Pre-Boost (U12.6)
~{DISCHG_L}: TIDA-01081E2_Controller (J10.3), TIDA-01081E2_LED_Buck (R15.2 U6.4)
~{SYNC_BUCK}: TIDA-01081E2_Controller (U21.28), TIDA-01081E2_LED_Buck (U4.1)
~{SYNC_EFUSE_&_BOOST}: TIDA-01081E2_CommonPower (U28.9), TIDA-01081E2_Controller (U21.39)
BOOST_VOUT/BUCK_VIN: TIDA-01081E2_Controller (R74.2), TIDA-01081E2_LED_Buck (6 pins), TIDA-01081E2_Pre-Boost (C25.1 C28.1 J21.1 TP7.1)
BUCK_OFF: TIDA-01081E2_Controller (U21.11), TIDA-01081E2_LED_Buck (U6.1)
BUCK_VOUT_OV: TIDA-01081E2_Controller (U21.14), TIDA-01081E2_LED_Buck (R14.1)
DIN: TIDA-01081E2_CommonPower (U28.8), TIDA-01081E2_Controller (U21.31), TIDA-01081E2_LED_Buck (U4.3)
EFUSE_IMON: TIDA-01081E2_CommonPower (R100.2), TIDA-01081E2_Controller (C49.1 U21.1)
EFUSE_OK: TIDA-01081E2_CommonPower (R97.2), TIDA-01081E2_Controller (U21.19)
EFUSE_ON: TIDA-01081E2_CommonPower (R99.1), TIDA-01081E2_Controller (U21.23)
EFUSE_VIN: TIDA-01081E2_CommonPower (8 pins), TIDA-01081E2_Controller (R137.2)
I_BOOST_ADJ: TIDA-01081E2_CommonPower (R105.2 R107.2 TP17.1), TIDA-01081E2_Pre-Boost (U10.6)
SCLK: TIDA-01081E2_CommonPower (U28.10), TIDA-01081E2_Controller (U21.30), TIDA-01081E2_LED_Buck (U4.2)
Trigger_In: TIDA-01081E2_Controller (U21.22), TIDA-01081E2_DigitalIO (TP24.1 U22.6)
Trigger_Out: TIDA-01081E2_Controller (U21.21), TIDA-01081E2_DigitalIO (U22.4)
UCA0RXD: TIDA-01081E2_Controller (U21.15), TIDA-01081E2_DigitalIO (U22.5)
UCA0TXD: TIDA-01081E2_Controller (U21.16), TIDA-01081E2_DigitalIO (U22.3)

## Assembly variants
001: not fitted C7 C15 C18 C29 C30 D4 D21 R4 R5 R10 R11 R23 R24 R26 R28 R31 R32 R37 R38 R58 R64 R98 R99 R114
